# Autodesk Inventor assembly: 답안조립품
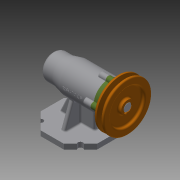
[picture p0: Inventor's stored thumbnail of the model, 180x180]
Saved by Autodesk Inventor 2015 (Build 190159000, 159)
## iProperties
Created: 2019-12
Part Number: 답안조립품
Document SubType Name: Assembly
Designer: 1021563
Author: 1021563
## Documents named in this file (12)
- C:\Users\1021563\Desktop\491204V1049\답안조립품.iam
- C:\Users\1021563\Desktop\491204V1049\V벨트풀리.ipt
- C:\Users\1021563\Desktop\491204V1049\멈춤나사 M3.ipt
- C:\Users\1021563\Desktop\491204V1049\베어링 6004.ipt
- C:\Users\1021563\Desktop\491204V1049\베어링 51202.ipt
- C:\Users\1021563\Desktop\491204V1049\본체.ipt
- C:\Users\1021563\Desktop\491204V1049\볼트 M4.ipt
- C:\Users\1021563\Desktop\491204V1049\어댑터슬리브.ipt
- C:\Users\1021563\Desktop\491204V1049\오일 실.ipt
- C:\Users\1021563\Desktop\491204V1049\축.ipt
- C:\Users\1021563\Desktop\491204V1049\커버.ipt
- C:\Users\1021563\Desktop\491204V1049\키 5 x 5 x 16.ipt
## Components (1 placed, 1 different names)
1. V벨트풀리:1 — 각도:2
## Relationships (1: Angle 1)
- 각도:2 [Angle]: V벨트풀리:1
